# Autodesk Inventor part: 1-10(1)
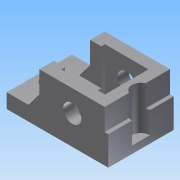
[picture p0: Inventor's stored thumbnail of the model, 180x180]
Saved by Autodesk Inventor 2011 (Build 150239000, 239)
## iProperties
Created: 2014-02
Part Number: 1-10(1)
Document SubType Name: Modeling
Designer: Administrator
Density: 1 g/cm^3
Author: Administrator
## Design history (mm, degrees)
sketch "草图1"
  geometry: L1 (-14, 9)-(14, 9); L2 (14, 9)-(14, -9); L3 (14, -9)-(-14, -9); L4 (-14, -9)-(-14, 9); 3 further points
  constraints: 8 end point, 2 midpoint, 2 parallel, 1 horizontal, 1 horizontal alignment, 1 perpendicular, 1 vertical alignment
extrude "拉伸1" new body sketch "草图1" distance "d0" = 4; taper "d1" = 0 deg
sketch "草图2"
  geometry: L1 (28, 4)-(0, 4) reference; L2 (0, 4)-(6, 4); L3 (6, 4)-(9, 8); L4 (9, 8)-(9, 14); L5 (9, 14)-(28, 14); L6 (28, 14)-(28, 4); 1 further point
  constraints: 10 end point, 3 perpendicular, 1 point on line
extrude "拉伸2" join sketch "草图2" distance "d2" = 4; taper "d3" = 0 deg
mirror "镜像1"
sketch "草图3"
  geometry: L1 (-8, -5)-(14, -5) reference; L2 (14, 5)-(14, -5) reference; L3 (14, 5)-(-8, 5) reference; L4 (14, 5)-(10, 5); L5 (10, -5)-(14, -5); L6 (10, -5)-(10, 5); L7 (14, 5)-(14, -5); 1 further point
  constraints: 8 end point, 2 collinear, 2 point on line, 1 perpendicular
extrude "拉伸3" join sketch "草图3" stored distance "d4" = 4; taper "d5" = 0 deg
sketch "草图4"
  geometry: C1 r 3 at (-10, 0); 1 further point
  constraints: 1 centre point
  dimensions: "d6" = 6 diameter of C1
extrude "拉伸4" cut sketch "草图4" stored distance "d7" = 4; taper "d8" = 0 deg
sketch "草图5"
  geometry: L1 (-10.064, -6)-(1.936, -6); L2 (1.936, -6)-(1.936, 6); L3 (1.936, 6)-(-10.064, 6); L4 (-10.064, 6)-(-10.064, -6); 4 further points
  constraints: 8 end point, 3 midpoint, 2 parallel, 1 horizontal, 1 horizontal alignment, 1 perpendicular
  dimensions: "d11" = 12 distance of L1.end L2.end; "d12" = 12 distance of L1.start L1.end
extrude "拉伸5" cut sketch "草图5" stored distance "d9" = 4; taper "d10" = 0 deg
sketch "草图6"
  geometry: L1 (19, 0)-(0, 0) reference; L2 (19, 18)-(19, 0) reference; L3 (19, 18)-(0, 18) reference; L4 (19, 0)-(18, 0); L5 (18, 0)-(18, 18); L6 (18, 18)-(19, 18); L7 (19, 0)-(19, 18); 1 further point
  constraints: 8 end point, 2 perpendicular, 2 point on line, 1 collinear
  dimensions: "d13" = 1 distance of L1.start L4.end
extrude "拉伸6" cut sketch "草图6" distance "d14" = 6; taper "d15" = 0 deg
sketch "草图7"
  geometry: L1 (19, 18)-(19, 0) reference; A1 r 2.5 centre (19, 9) between (19, 11.5) and (19, 6.5); 1 further point
  constraints: 2 point on circle, 2 point on line, 1 centre point, 1 midpoint
  dimensions: "d17" = 5 diameter of A1
extrude "拉伸7" cut sketch "草图7" distance "d18" = 12; taper "d19" = 0 deg
hole "Hole1" diameter "d22" = 5; stored, may be unused: countersink angle "d26" = 90 deg, drill point angle "d28" = 118 deg; dims "d20" = 6, "d21" = 6, "d23" = 6, "d24" = 4, "d25" = 2, "d27" = 8
mirror "镜像2"
node "实体1"
